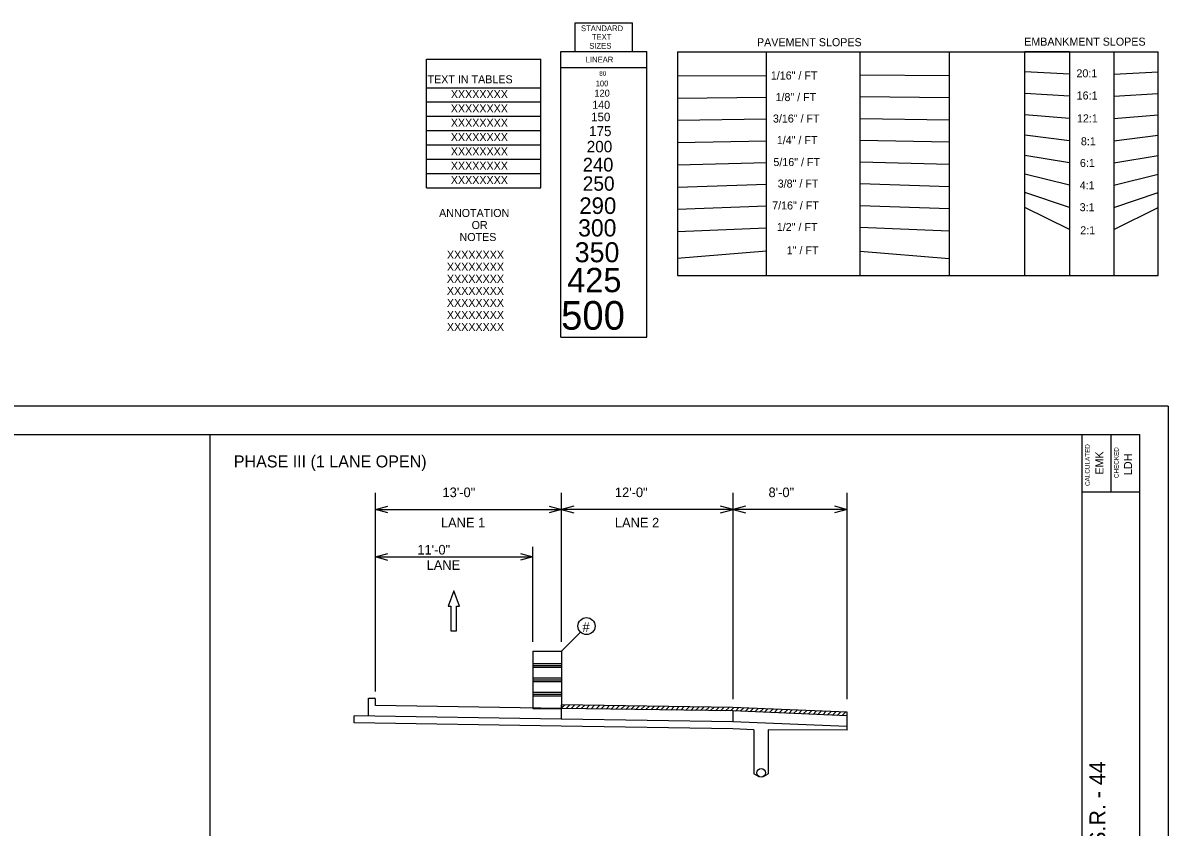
# Model space of a CAD drawing. Extents: x -161 to 291, y -369 to 173.
# Drawn here: x -104.8 to -24.7, y -214.9 to -158.7 of the extents above; entities that cross this region are included whole.
import ezdxf

# ---------------------------------------------------------------- set-up
doc = ezdxf.new("R2010")
doc.units = 0
for name, color, linetype in [('Level 1', 7, 'Continuous'), ('Level 11', 7, 'Continuous'), ('Level 25', 7, 'Continuous'), ('Level 26', 7, 'Continuous'), ('Level 6', 7, 'Continuous'), ('Level 7', 7, 'Continuous')]:
    doc.layers.add(name, color=color, linetype=linetype)

msp = doc.modelspace()

# ---------------------------------------------------------------- linework, layer by layer
at = {"layer": 'Level 1'}
for p, q in [((-66.199, -160.657), (-66.199, -158.657)), ((-66.199, -158.657), (-62.2, -158.657)), ((-62.2, -160.657), (-62.2, -158.657)), ((-67.199, -160.657), (-61.199, -160.657)), ((-67.199, -180.623), (-67.199, -160.657)), ((-61.199, -180.623), (-61.199, -160.657)), ((-59.044, -160.677), (-59.044, -176.299)), ((-59.044, -160.677), (-25.435, -160.677)), ((-52.832, -176.299), (-52.832, -160.677)), ((-46.269, -176.283), (-46.269, -160.677)), ((-40.062, -160.677), (-40.062, -176.299)), ((-34.75, -160.677), (-34.75, -160.677)), ((-31.646, -160.677), (-34.75, -160.677)), ((-34.75, -176.299), (-34.75, -160.677)), ((-31.646, -160.677), (-31.646, -176.299)), ((-28.538, -160.677), (-25.435, -160.677)), ((-28.538, -160.677), (-28.538, -176.299)), ((-25.435, -176.299), (-25.435, -160.677)), ((-76.605, -170.182), (-76.605, -161.182)), ((-76.605, -161.182), (-68.606, -161.182)), ((-68.606, -170.182), (-68.606, -161.182)), ((-67.199, -161.769), (-61.199, -161.769)), ((-59.044, -162.361), (-52.832, -162.324)), ((-40.062, -162.345), (-46.269, -162.309)), ((-31.646, -162.232), (-34.75, -162.077)), ((-28.538, -162.232), (-25.435, -162.077)), ((-76.605, -163.182), (-68.606, -163.182)), ((-76.605, -164.182), (-68.606, -164.182)), ((-59.044, -163.913), (-52.832, -163.845)), ((-40.062, -163.897), (-46.269, -163.829)), ((-31.646, -163.785), (-34.75, -163.589)), ((-28.538, -163.785), (-25.435, -163.589)), ((-76.605, -165.182), (-68.606, -165.182)), ((-59.044, -165.464), (-52.832, -165.368)), ((-40.062, -165.448), (-46.269, -165.352)), ((-31.646, -165.337), (-34.75, -165.077)), ((-28.538, -165.337), (-25.435, -165.077)), ((-76.605, -166.182), (-68.606, -166.182)), ((-31.646, -166.888), (-34.75, -166.5)), ((-28.538, -166.888), (-25.435, -166.5)), ((-76.605, -167.182), (-68.606, -167.182)), ((-59.044, -167.016), (-52.832, -166.888)), ((-40.062, -167), (-46.269, -166.872)), ((-76.605, -168.182), (-68.606, -168.182)), ((-31.646, -168.44), (-34.75, -167.924)), ((-28.538, -168.44), (-25.435, -167.924)), ((-59.044, -168.568), (-52.832, -168.408)), ((-40.062, -168.552), (-46.269, -168.392)), ((-76.605, -169.181), (-68.606, -169.181)), ((-31.646, -169.996), (-34.75, -169.216)), ((-28.538, -169.996), (-25.435, -169.216)), ((-76.605, -170.182), (-68.606, -170.182)), ((-59.044, -170.124), (-52.832, -169.928)), ((-40.062, -170.108), (-46.269, -169.912)), ((-31.646, -171.548), (-34.75, -170.512)), ((-28.538, -171.548), (-25.435, -170.512)), ((-59.044, -171.676), (-52.832, -171.448)), ((-40.062, -171.66), (-46.269, -171.432)), ((-31.646, -173.1), (-34.75, -171.548)), ((-28.538, -173.1), (-25.435, -171.548)), ((-59.044, -173.228), (-52.832, -172.968)), ((-40.062, -173.212), (-46.269, -172.952)), ((-59.076, -175.095), (-52.832, -174.575)), ((-40.062, -175.143), (-46.269, -174.627)), ((-59.044, -176.299), (-52.832, -176.299)), ((-52.832, -176.299), (-25.435, -176.299)), ((-67.199, -180.623), (-61.199, -180.623)), ((-24.739, -185.431), (-160.725, -185.431)), ((-24.739, -185.431), (-24.739, -273.422)), ((-152.726, -187.43), (-26.739, -187.43)), ((-91.732, -224.426), (-91.732, -187.43)), ((-30.738, -204.429), (-30.738, -187.43)), ((-28.738, -187.43), (-28.738, -191.43)), ((-26.739, -187.43), (-26.739, -271.422)), ((-30.738, -191.43), (-26.739, -191.43)), ((-30.738, -249.424), (-30.738, -204.429))]:
    msp.add_line(p, q, dxfattribs=at)
at = {"layer": 'Level 11'}
for p, q in [((-80.666, -207.096), (-80.666, -205.856)), ((-80.666, -205.856), (-80.249, -205.856)), ((-80.166, -206.356), (-80.166, -205.939)), ((-67.166, -206.556), (-80.166, -206.356)), ((-67.167, -207.304), (-67.167, -206.556)), ((-67.166, -206.556), (-67.166, -206.306)), ((-67.166, -206.541), (-66.936, -206.31)), ((-55.19, -206.741), (-67.166, -206.556)), ((-55.193, -206.491), (-67.163, -206.306)), ((-66.834, -206.562), (-66.587, -206.315)), ((-66.485, -206.567), (-66.239, -206.321)), ((-66.137, -206.572), (-65.891, -206.326)), ((-65.789, -206.578), (-65.543, -206.331)), ((-65.441, -206.583), (-65.195, -206.337)), ((-65.093, -206.588), (-64.846, -206.342)), ((-64.745, -206.594), (-64.498, -206.348)), ((-64.396, -206.599), (-64.15, -206.353)), ((-64.048, -206.605), (-63.802, -206.358)), ((-63.7, -206.61), (-63.454, -206.364)), ((-63.352, -206.615), (-63.106, -206.369)), ((-63.004, -206.621), (-62.757, -206.374)), ((-62.656, -206.626), (-62.409, -206.38)), ((-62.307, -206.631), (-62.061, -206.385)), ((-61.959, -206.637), (-61.713, -206.391)), ((-61.611, -206.642), (-61.365, -206.396)), ((-61.263, -206.648), (-61.017, -206.401)), ((-60.915, -206.653), (-60.668, -206.407)), ((-60.566, -206.658), (-60.32, -206.412)), ((-60.218, -206.664), (-59.972, -206.417)), ((-59.87, -206.669), (-59.624, -206.423)), ((-59.522, -206.675), (-59.276, -206.428)), ((-59.174, -206.68), (-58.927, -206.434)), ((-58.826, -206.685), (-58.579, -206.439)), ((-58.477, -206.691), (-58.231, -206.444)), ((-58.129, -206.696), (-57.883, -206.45)), ((-57.781, -206.701), (-57.535, -206.455)), ((-57.433, -206.707), (-57.187, -206.46)), ((-57.085, -206.712), (-56.838, -206.466)), ((-56.737, -206.718), (-56.49, -206.471)), ((-56.388, -206.723), (-56.142, -206.477)), ((-56.04, -206.728), (-55.794, -206.482)), ((-55.692, -206.734), (-55.446, -206.487)), ((-55.344, -206.739), (-55.1, -206.495)), ((-47.193, -206.826), (-55.193, -206.491)), ((-55.001, -206.749), (-54.761, -206.509)), ((-54.661, -206.764), (-54.421, -206.524)), ((-54.322, -206.778), (-54.082, -206.538)), ((-53.983, -206.792), (-53.743, -206.552)), ((-53.643, -206.806), (-53.403, -206.566)), ((-53.304, -206.82), (-53.064, -206.58)), ((-52.965, -206.835), (-52.725, -206.595)), ((-52.625, -206.849), (-52.385, -206.609)), ((-52.286, -206.863), (-52.046, -206.623)), ((-51.947, -206.877), (-51.707, -206.637)), ((-67.182, -207.304), (-81.668, -207.08)), ((-81.666, -207.58), (-81.666, -207.08)), ((-55.173, -207.49), (-67.167, -207.304)), ((-47.193, -207.076), (-55.19, -206.741)), ((-55.167, -207.49), (-55.167, -206.742)), ((-51.607, -206.892), (-51.367, -206.652)), ((-51.268, -206.906), (-51.028, -206.666)), ((-50.929, -206.92), (-50.689, -206.68)), ((-50.589, -206.934), (-50.349, -206.694)), ((-50.25, -206.948), (-50.01, -206.708)), ((-49.911, -206.963), (-49.671, -206.723)), ((-49.571, -206.977), (-49.331, -206.737)), ((-49.232, -206.991), (-48.992, -206.751)), ((-48.893, -207.005), (-48.653, -206.765)), ((-48.553, -207.019), (-48.313, -206.779)), ((-48.214, -207.034), (-47.974, -206.794)), ((-47.874, -207.048), (-47.635, -206.808)), ((-47.535, -207.062), (-47.295, -206.822)), ((-47.196, -207.076), (-47.193, -207.074)), ((-47.193, -208.074), (-47.193, -206.826)), ((-67.183, -207.804), (-81.668, -207.58)), ((-55.191, -207.989), (-67.181, -207.804)), ((-53.719, -208.051), (-55.191, -207.989)), ((-47.197, -207.824), (-55.173, -207.49)), ((-53.715, -208.051), (-53.715, -211.142)), ((-47.193, -208.074), (-52.716, -208.054)), ((-52.715, -208.054), (-52.715, -211.132)), ((-53.328, -211.334), (-53.715, -211.142)), ((-53.038, -211.323), (-52.715, -211.132))]:
    msp.add_line(p, q, dxfattribs=at)
msp.add_circle((-53.193, -211.062), 0.304, dxfattribs=at)
msp.add_arc((-80.249, -205.939), 0.083, 0, 90, dxfattribs=at)
at = {"layer": 'Level 25'}
for p, q in [((-69.166, -202.556), (-69.166, -206.556)), ((-69.166, -202.556), (-67.166, -202.556)), ((-67.166, -202.556), (-67.166, -206.556)), ((-69.166, -203.431), (-67.166, -203.431)), ((-69.166, -203.556), (-67.166, -203.556)), ((-69.166, -203.681), (-67.166, -203.681)), ((-69.166, -204.431), (-67.166, -204.431)), ((-69.166, -204.556), (-67.166, -204.556)), ((-69.166, -204.681), (-67.166, -204.681)), ((-69.166, -205.431), (-67.166, -205.431)), ((-69.166, -205.556), (-67.166, -205.556)), ((-69.166, -205.681), (-67.166, -205.681)), ((-69.166, -206.556), (-67.166, -206.556))]:
    msp.add_line(p, q, dxfattribs=at)
at = {"layer": 'Level 26'}
for p, q in [((-80.167, -205.379), (-80.167, -191.496)), ((-67.167, -201.918), (-67.167, -191.496)), ((-55.167, -205.909), (-55.167, -191.496)), ((-47.193, -205.908), (-47.193, -191.496)), ((-80.167, -192.656), (-67.167, -192.656)), ((-55.167, -192.656), (-67.167, -192.656)), ((-47.193, -192.656), (-55.167, -192.656)), ((-69.167, -201.918), (-69.167, -195.265)), ((-80.167, -195.976), (-69.167, -195.976)), ((-67.166, -202.556), (-65.837, -201.232))]:
    msp.add_line(p, q, dxfattribs=at)
for points in [[(-79.3, -192.895), (-80.167, -192.656), (-79.3, -192.425)], [(-68.033, -192.417), (-67.167, -192.656), (-68.033, -192.887)], [(-66.3, -192.417), (-67.167, -192.656), (-66.3, -192.887)], [(-56.035, -192.896), (-55.167, -192.656), (-56.035, -192.424)], [(-54.3, -192.417), (-55.167, -192.656), (-54.3, -192.887)], [(-48.061, -192.416), (-47.193, -192.656), (-48.061, -192.887)], [(-79.3, -196.216), (-80.167, -195.976), (-79.3, -195.745)], [(-70.033, -195.737), (-69.167, -195.976), (-70.033, -196.207)]]:
    msp.add_lwpolyline(points, dxfattribs=at)
msp.add_circle((-65.415, -200.809), 0.597, dxfattribs=at)
at = {"layer": 'Level 7'}
for p, q in [((-74.7, -198.334), (-75.097, -199.405)), ((-74.297, -199.405), (-74.7, -198.334)), ((-75.097, -199.405), (-74.892, -199.405)), ((-74.892, -199.405), (-74.892, -201.132)), ((-74.502, -201.132), (-74.502, -199.405)), ((-74.502, -199.405), (-74.297, -199.405)), ((-74.892, -201.132), (-74.502, -201.132))]:
    msp.add_line(p, q, dxfattribs=at)

# ---------------------------------------------------------------- texts
at = {"layer": 'Level 1'}
for s, height, p in [('STANDARD', 0.4, (-65.799, -159.233)), ('SIZES', 0.4, (-65.223, -160.457)), ('TEXT', 0.4, (-65.039, -159.837)), ('PAVEMENT SLOPES', 0.55993, (-53.492, -160.285)), ('EMBANKMENT SLOPES', 0.55993, (-34.802, -160.245)), ('LINEAR', 0.4, (-65.471, -161.421)), ('80', 0.32, (-64.523, -162.357)), ('1/16" / FT', 0.5599, (-52.524, -162.612)), ('20:1', 0.5599, (-31.15, -162.461)), ('120', 0.4799, (-64.859, -163.805)), ('100', 0.4, (-64.775, -163.089)), ('140', 0.5599, (-65.015, -164.66)), ('1/8" / FT', 0.5599, (-52.192, -164.121)), ('16:1', 0.5599, (-31.134, -164.009)), ('150', 0.5999, (-65.087, -165.528)), ('3/16" / FT', 0.5599, (-52.376, -165.62)), ('12:1', 0.5599, (-31.114, -165.608)), ('175', 0.6999, (-65.231, -166.568)), ('1/4" / FT', 0.5599, (-52.104, -167.124)), ('200', 0.7999, (-65.399, -167.7)), ('8:1', 0.5599, (-30.838, -167.208)), ('240', 0.9599, (-65.675, -169.044)), ('5/16" / FT', 0.5599, (-52.344, -168.66)), ('6:1', 0.5599, (-30.906, -168.724)), ('250', 0.9999, (-65.679, -170.384)), ('3/8" / FT', 0.5599, (-52.041, -170.164)), ('4:1', 0.5599, (-30.918, -170.284)), ('290', 1.1599, (-65.919, -172.008)), ('7/16" / FT', 0.5599, (-52.428, -171.696)), ('3:1', 0.5599, (-30.923, -171.816)), ('300', 1.1999, (-65.999, -173.58)), ('1/2" / FT', 0.5599, (-52.104, -173.2)), ('2:1', 0.5599, (-30.883, -173.428)), ('350', 1.3998, (-66.239, -175.383)), ('1" / FT', 0.5599, (-51.412, -174.828)), ('425', 1.6998, (-66.763, -177.475)), ('500', 1.9998, (-67.191, -180.095))]:
    msp.add_text(s, height=height, dxfattribs=at).set_placement(p)
for s, height, p in [('CALCULATED', 0.32, (-30.221, -191.016)), ('EMK', 0.5599, (-29.263, -190.223)), ('CHECKED', 0.32, (-28.199, -190.467)), ('LDH', 0.5599, (-27.264, -190.254)), ('MAINTENANCE OF TRAFFIC DETAILS S.R. - 44', 1.11989, (-29.118, -243.372))]:
    msp.add_text(s, height=height, rotation=90, dxfattribs=at).set_placement(p)
at = {"layer": 'Level 26'}
for s, height, p in [('TEXT IN TABLES', 0.55994, (-76.532, -162.879)), ('XXXXXXXX', 0.5599, (-74.904, -163.915)), ('XXXXXXXX', 0.5599, (-74.904, -164.914)), ('XXXXXXXX', 0.5599, (-74.904, -165.914)), ('XXXXXXXX', 0.5599, (-74.904, -166.914)), ('XXXXXXXX', 0.5599, (-74.904, -167.914)), ('XXXXXXXX', 0.5599, (-74.904, -168.914)), ('XXXXXXXX', 0.5599, (-74.904, -169.914)), ('ANNOTATION', 0.5599, (-75.723, -172.219)), ('OR', 0.5599, (-73.449, -173.059)), ('NOTES', 0.5599, (-74.296, -173.899)), ('XXXXXXXX', 0.5599, (-75.178, -175.141)), ('XXXXXXXX', 0.5599, (-75.178, -175.981)), ('XXXXXXXX', 0.5599, (-75.178, -176.821)), ('XXXXXXXX', 0.5599, (-75.178, -177.661)), ('XXXXXXXX', 0.5599, (-75.178, -178.5)), ('XXXXXXXX', 0.5599, (-75.178, -179.34)), ('XXXXXXXX', 0.5599, (-75.178, -180.18)), ('13\'-0"', 0.672, (-75.485, -191.798)), ('12\'-0"', 0.672, (-63.428, -191.798)), ('8\'-0"', 0.672, (-52.683, -191.798)), ('LANE 1', 0.672, (-75.596, -193.915)), ('LANE 2', 0.672, (-63.428, -193.915)), ('11\'-0"', 0.672, (-77.242, -195.808)), ('LANE', 0.672, (-76.596, -196.88)), ('#', 0.672, (-65.698, -201.212))]:
    msp.add_text(s, height=height, dxfattribs=at).set_placement(p)
at = {"layer": 'Level 6'}
msp.add_text('PHASE III (1 LANE OPEN)', height=0.84, dxfattribs=at).set_placement((-90.082, -189.722))

doc.saveas('drawing.dxf')
